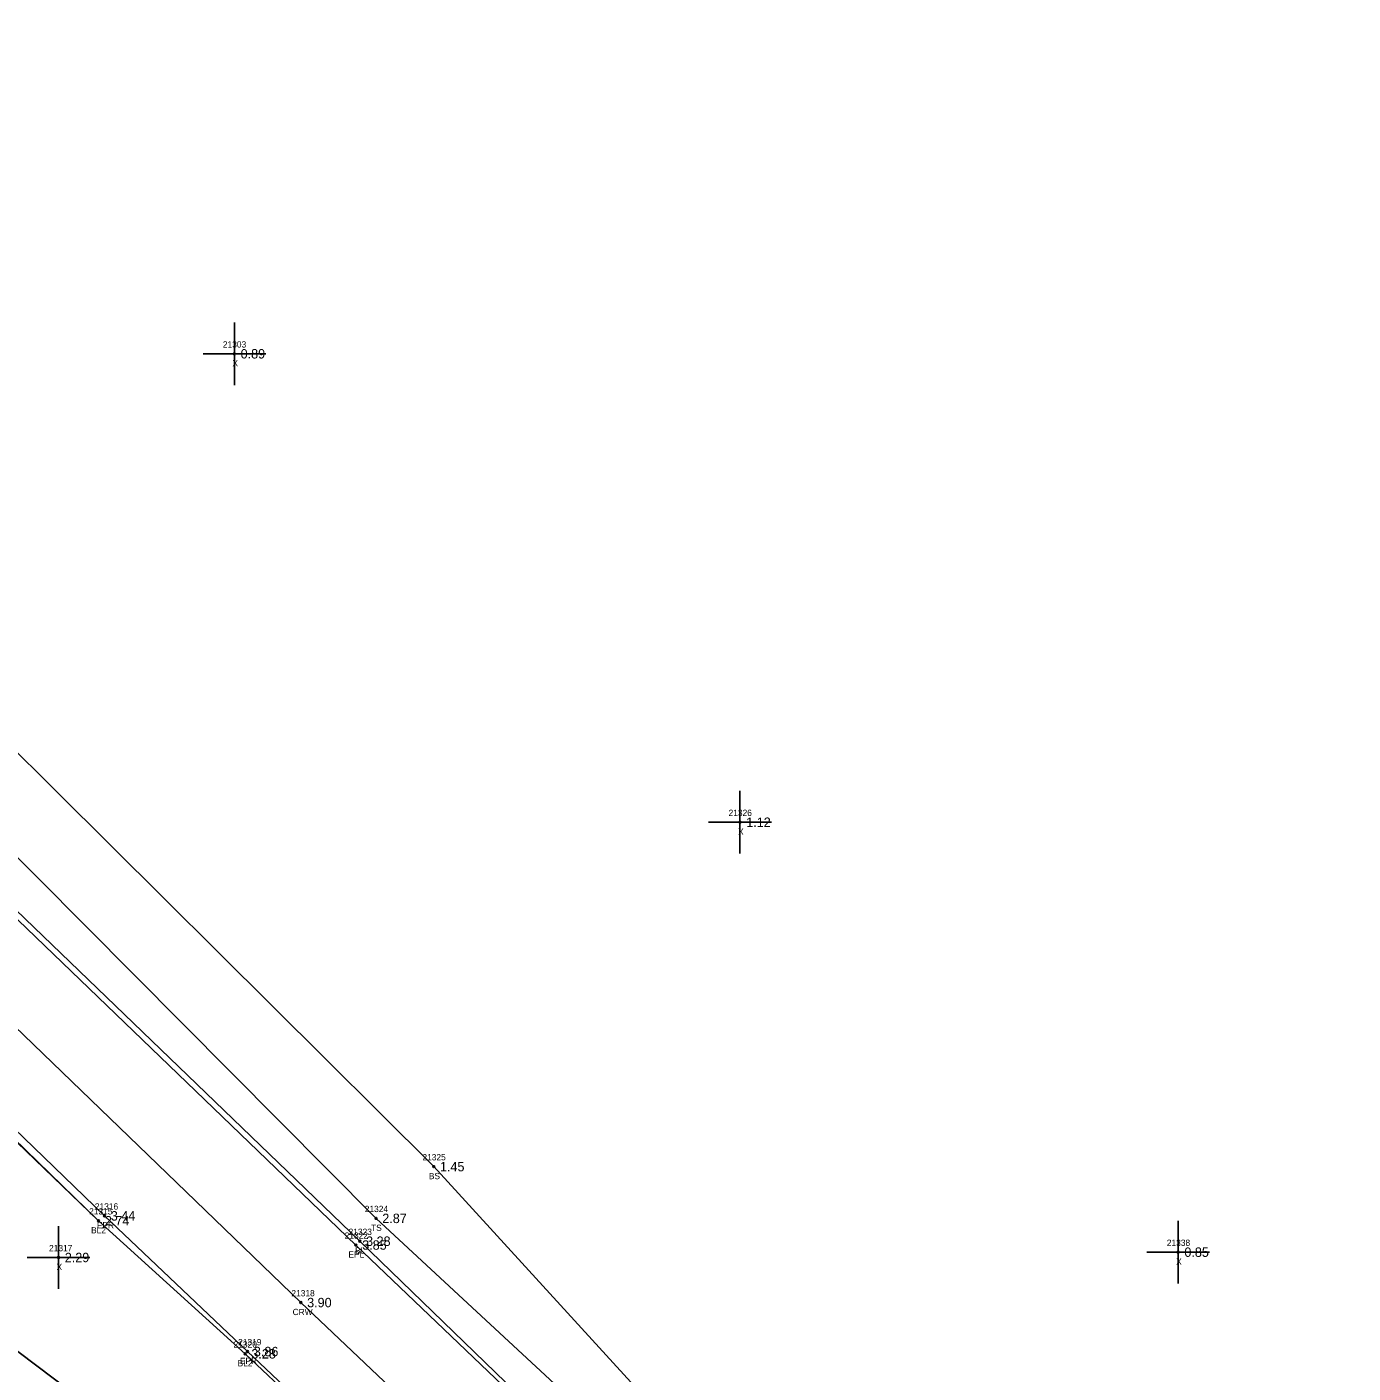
# Model space of a CAD drawing. Extents: x 2608745 to 2610333, y 641917 to 643463.
# Drawn here: x 2609885.8 to 2610097.4, y 642286 to 642500.7 of the extents above; entities that cross this region are included whole.
import ezdxf

# ---------------------------------------------------------------- set-up
doc = ezdxf.new("R2010")
doc.units = 0
for name, color, linetype in [('RD_DTM_BkLn1', 7, 'Continuous'), ('RD_DTM_BkLn2', 7, 'Continuous'), ('RD_DTM_BkLn_txCode', 7, 'Continuous'), ('RD_EX_H2O', 7, 'Continuous'), ('RD_EX_Misc', 7, 'Continuous'), ('RD_EX_Misc_txCode', 7, 'Continuous'), ('RD_EX_Road', 7, 'Continuous'), ('RD_EX_Road_txCode', 7, 'Continuous'), ('RD_EX_TX_Misc_ELEV', 7, 'Continuous'), ('RD_EX_TX_Road_ELEV', 7, 'Continuous'), ('RD_HC_Survey_ELEV', 7, 'Continuous'), ('RD_HC_Survey_txCode', 7, 'Continuous'), ('RD_SMD_Locator', 7, 'Continuous')]:
    doc.layers.add(name, color=color, linetype=linetype)

msp = doc.modelspace()

# ---------------------------------------------------------------- linework, layer by layer
at = {"layer": 'RD_DTM_BkLn1'}
for points in [[(2609568.4, 642647.43), (2609618.95, 642597.92), (2609693.89, 642525.38), (2609771.33, 642450.27), (2609850.26, 642373.69), (2609929.54, 642297.24), (2610000.01, 642230.49), (2610078.71, 642154.75), (2610156.09, 642080.44), (2610235.53, 642002.94), (2610263.59, 641975.77)], [(2609627.58, 642607.09), (2609630.23, 642605.37), (2609646.31, 642589.45), (2609703.16, 642535.02), (2609781.51, 642459.84), (2609859.44, 642383.51), (2609938.95, 642307.03), (2610008.76, 642239.49), (2610086.74, 642162.99), (2610105.31, 642145.89), (2610105.31, 642145.89), (2610140.26, 642113.1), (2610153.89, 642100.28), (2610164.72, 642089.82), (2610189.2, 642065.46)], [(2609638.64, 642561.68), (2609646.49, 642552.99), (2609655.41, 642544.68), (2609682.3, 642518.46), (2609696.97, 642504.35), (2609720.79, 642481.57), (2609738.97, 642465.02), (2609753.66, 642450.39), (2609762.69, 642441.83), (2609780.95, 642423.34), (2609796.2, 642407.99), (2609840.83, 642364.55), (2609897.27, 642310.29), (2609920.64, 642289.07), (2609961.88, 642250.25), (2609968.31, 642243.41), (2609978.92, 642233.98)]]:
    msp.add_lwpolyline(points, dxfattribs=at)
at = {"layer": 'RD_DTM_BkLn2'}
for points in [[(2609582.66, 642657.54), (2609585.75, 642657.34), (2609622.53, 642623.2), (2609632.13, 642611.9), (2609647.4, 642591.36), (2609682.93, 642558.52), (2609706.14, 642537.77), (2609755.54, 642496.98), (2609786.05, 642464.88), (2609864.24, 642388.44), (2609941.53, 642310.67), (2610012.94, 642244.46), (2610082.83, 642179.18), (2610093.52, 642170.29)], [(2609755.54, 642496.98), (2609777.06, 642487.55), (2609794.23, 642472.67), (2609873.31, 642395.79), (2609950.73, 642318.92), (2610015.83, 642247.73), (2610085.46, 642180.03), (2610093.52, 642170.29)]]:
    msp.add_lwpolyline(points, dxfattribs=at)
at = {"layer": 'RD_EX_H2O'}
msp.add_lwpolyline([(2609550.15, 642638.19), (2609560.64, 642608.55), (2609596.58, 642544.67), (2609665.26, 642493.63), (2609726.89, 642435.57), (2609728.97, 642442.01), (2609745.88, 642433.78), (2609753.45, 642414.77), (2609764.24, 642411.87), (2609765.65, 642391.82), (2609764.35, 642384.35), (2609816.5, 642340.65), (2609898.67, 642278.63), (2609932.36, 642236.09), (2609918.8, 642192.33)], dxfattribs=at)
at = {"layer": 'RD_EX_Misc'}
for p, q in [((2609918.93, 642443.56), (2609918.93, 642453.56)), ((2609913.93, 642448.56), (2609923.93, 642448.56)), ((2609999.59, 642368.85), (2609999.59, 642378.85)), ((2609994.59, 642373.85), (2610004.59, 642373.85)), ((2609890.88, 642299.43), (2609890.88, 642309.43)), ((2610069.48, 642300.28), (2610069.48, 642310.28)), ((2610064.48, 642305.28), (2610074.48, 642305.28)), ((2609885.88, 642304.43), (2609895.88, 642304.43))]:
    msp.add_line(p, q, dxfattribs=at)
at = {"layer": 'RD_EX_Road'}
for points in [[(2609576.61, 642656.06), (2609590.88, 642642.24), (2609605.19, 642628.78), (2609627.58, 642607.09), (2609646.03, 642589.11), (2609702.18, 642534.04), (2609780.35, 642458.95), (2609858.79, 642382.83), (2609938.32, 642306.42), (2610008.62, 642239.32), (2610086.3, 642162.54), (2610164.18, 642089.49), (2610189.2, 642065.46), (2610214.78, 642040.19), (2610225.86, 642030.16), (2610226.32, 642028.39), (2610235.43, 642019.75), (2610260.23, 641995.63), (2610272.39, 641983.25)], [(2609780.95, 642423.34), (2609796.46, 642408.17), (2609841.07, 642364.89), (2609897.27, 642310.29)], [(2609841.8, 642365.54), (2609898.22, 642311.07), (2609921.04, 642289.43), (2609962.12, 642250.55), (2609969.04, 642244.08), (2609979.13, 642234.19), (2609992.4, 642221.66), (2610004.86, 642210.01), (2610027, 642188.8), (2610067.64, 642149.14), (2610070.8, 642146.19), (2610073.96, 642143.05), (2610116.51, 642103.01), (2610119.68, 642100.06), (2610135.09, 642085.92), (2610148.33, 642073.03), (2610165.14, 642055.61), (2610179.59, 642041.57), (2610196.49, 642024.71), (2610209.86, 642011.42), (2610228.39, 641994.06), (2610252.93, 641970.08), (2610256.35, 641966.74)]]:
    msp.add_lwpolyline(points, dxfattribs=at)
at = {"layer": 'RD_SMD_Locator'}
for centre in [(2609918.93, 642448.56), (2609999.59, 642373.85), (2609950.73, 642318.92), (2609898.22, 642311.07), (2609897.27, 642310.29), (2609941.53, 642310.67), (2609938.95, 642307.03), (2609890.88, 642304.43), (2609938.32, 642306.42), (2610069.48, 642305.28), (2609929.54, 642297.24), (2609921.04, 642289.43), (2609920.64, 642289.07)]:
    msp.add_circle(centre, 0.15, dxfattribs=at)

# ---------------------------------------------------------------- texts
at = {"layer": 'RD_DTM_BkLn_txCode'}
for s, p in [('21325', (2609948.93, 642319.92)), ('BS', (2609949.95, 642316.92)), ('21315', (2609895.76, 642311.29)), ('21324', (2609939.73, 642311.67)), ('BL2', (2609896.07, 642308.29)), ('21323', (2609937.15, 642308.03)), ('TS', (2609940.73, 642308.67)), ('BL', (2609938.19, 642305.03)), ('21320', (2609918.81, 642290.07)), ('BL2', (2609919.44, 642287.07))]:
    msp.add_text(s, height=1, dxfattribs=at).set_placement(p)
at = {"layer": 'RD_EX_Misc_txCode'}
for s, p in [('21303', (2609917.1, 642449.56)), ('X', (2609918.62, 642446.56)), ('21326', (2609997.77, 642374.85)), ('X', (2609999.28, 642371.85)), ('21338', (2610067.68, 642306.28)), ('21317', (2609889.37, 642305.43)), ('X', (2609890.56, 642302.43)), ('X', (2610069.16, 642303.28))]:
    msp.add_text(s, height=1, dxfattribs=at).set_placement(p)
at = {"layer": 'RD_EX_Road_txCode'}
for s, p in [('21316', (2609896.68, 642312.07)), ('EPR', (2609896.99, 642309.07)), ('21322', (2609936.53, 642307.42)), ('EPL', (2609937.12, 642304.42)), ('21319', (2609919.53, 642290.43)), ('EPR', (2609919.81, 642287.43))]:
    msp.add_text(s, height=1, dxfattribs=at).set_placement(p)
at = {"layer": 'RD_EX_TX_Misc_ELEV'}
for s, p in [('0.89', (2609919.93, 642447.81)), ('1.12', (2610000.59, 642373.1)), ('1.45', (2609951.73, 642318.17)), ('2.74', (2609898.27, 642309.54)), ('2.87', (2609942.53, 642309.92)), ('3.28', (2609939.95, 642306.28)), ('2.29', (2609891.88, 642303.68)), ('0.85', (2610070.48, 642304.53)), ('3.28', (2609921.64, 642288.32))]:
    msp.add_text(s, height=1.5, dxfattribs=at).set_placement(p)
at = {"layer": 'RD_EX_TX_Road_ELEV'}
for s, p in [('3.44', (2609899.22, 642310.32)), ('3.85', (2609939.32, 642305.67)), ('3.86', (2609922.04, 642288.68))]:
    msp.add_text(s, height=1.5, dxfattribs=at).set_placement(p)
at = {"layer": 'RD_HC_Survey_ELEV'}
msp.add_text('3.90', height=1.5, dxfattribs=at).set_placement((2609930.54, 642296.49))
at = {"layer": 'RD_HC_Survey_txCode'}
for s, p in [('21318', (2609928.03, 642298.24)), ('CRW', (2609928.22, 642295.24))]:
    msp.add_text(s, height=1, dxfattribs=at).set_placement(p)

doc.saveas('drawing.dxf')
